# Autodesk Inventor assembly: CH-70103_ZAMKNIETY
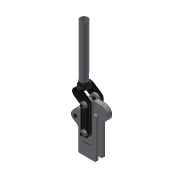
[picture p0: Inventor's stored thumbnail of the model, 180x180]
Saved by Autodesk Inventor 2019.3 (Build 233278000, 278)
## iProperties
Company: Î¢ÈíÖÐ¹ú
Created: 2012-10
Part Number: CH-70103_ZAMKNIETY
Material: Ogólny
Description: STEP AP203
Document SubType Name: Assembly
Designer: CADENGINEERING4
Stock Number: DOCISKI CIĘŻKIE
Sending System: SolidWorks 2010
Preprocessor: SwSTEP 2.0
Title: CH-70103.STEP
Author: Î¢ÈíÓÃ»§
Revision Number: ÈÎºÎ
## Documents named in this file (11)
- D:\Vault_2016\Projekty\NASZ KATALOG\CLAMPTEK\STRONA\Heavy duty weldables\CH-70103\CH-70103_ZAMKNIETY.iam
- D:\Vault_2016\Projekty\NASZ KATALOG\CLAMPTEK\STRONA\Heavy duty weldables\CH-70103\3-8-16 LOCK NUT.ipt
- D:\Vault_2016\Projekty\NASZ KATALOG\CLAMPTEK\STRONA\Heavy duty weldables\CH-70103\70103-10.ipt
- D:\Vault_2016\Projekty\NASZ KATALOG\CLAMPTEK\STRONA\Heavy duty weldables\CH-70103\70103-06.ipt
- D:\Vault_2016\Projekty\NASZ KATALOG\CLAMPTEK\STRONA\Heavy duty weldables\CH-70103\70103-04.ipt
- D:\Vault_2016\Projekty\NASZ KATALOG\CLAMPTEK\STRONA\Heavy duty weldables\CH-70103\70103-08.ipt
- D:\Vault_2016\Projekty\NASZ KATALOG\CLAMPTEK\STRONA\Heavy duty weldables\CH-70103\70103-02.ipt
- D:\Vault_2016\Projekty\NASZ KATALOG\CLAMPTEK\STRONA\Heavy duty weldables\CH-70103\70103-01.ipt
- D:\Vault_2016\Projekty\NASZ KATALOG\CLAMPTEK\STRONA\Heavy duty weldables\CH-70103\70103-03.ipt
- D:\Vault_2016\Projekty\NASZ KATALOG\CLAMPTEK\STRONA\Heavy duty weldables\CH-70103\70103-07.ipt
- D:\Vault_2016\Projekty\NASZ KATALOG\CLAMPTEK\STRONA\Heavy duty weldables\CH-70103\70103-05.ipt
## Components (17 placed, 17 different names)
1. 3-8-16 LOCK NUT_1
2. 70103-10_2
3. 70103-06_3
4. 70103-04_4
5. 70103-08_5
6. 70103-02_6
7. 3-8-16 LOCK NUT_7
8. 70103-01_8
9. 70103-06_9
10. 70103-03_10
11. 70103-07_11
12. 70103-10_12
13. 70103-07_13
14. 70103-05_14
15. 70103-08_15
16. 70103-03_16
17. 70103-04_17
